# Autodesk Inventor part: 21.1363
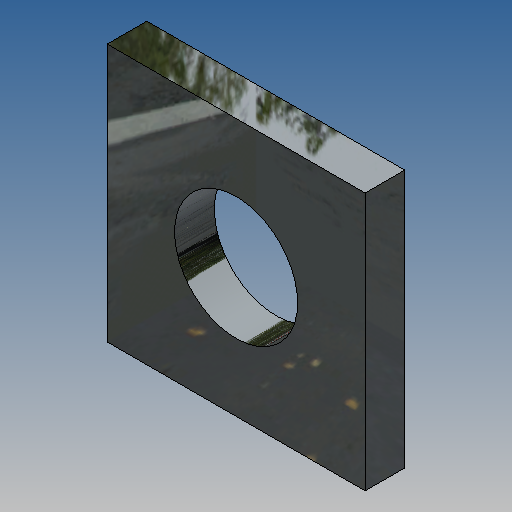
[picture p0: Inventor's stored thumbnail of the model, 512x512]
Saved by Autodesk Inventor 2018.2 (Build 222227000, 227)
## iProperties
Created: 2006-12
Part Number: 21.1363
Document SubType Name: Modeling
Designer: Andy Moles
Material: Steel, Mild
Density: 7.86 g/cm^3
Description: M6 SQUARE WASHER
Appearance: Zinc
Author: Andy Moles
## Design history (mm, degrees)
sketch "Sketch1"
  geometry: L1 (-6.5, -6.5)-(6.5, -6.5); L2 (6.5, -6.5)-(6.5, 6.5); L3 (6.5, 6.5)-(-6.5, 6.5); L4 (-6.5, 6.5)-(-6.5, -6.5); L5 (-6.5, -6.5)-(6.5, 6.5); C1 r 3.1 at (0, 0); 2 further points
  constraints: 10 end point, 2 coincident, 2 parallel, 1 centre point, 1 horizontal, 1 midpoint, 1 perpendicular
  dimensions: "d0" = 13 distance of L2.end L3.end; "d1" = 13 distance of L3.end L1.start; "HOLE_DIA" = 6.2 diameter of C1
extrude "Extrusion1" new body sketch "Sketch1" distance "d3" = 2; taper "d4" = 0 deg
body "Solid1"
